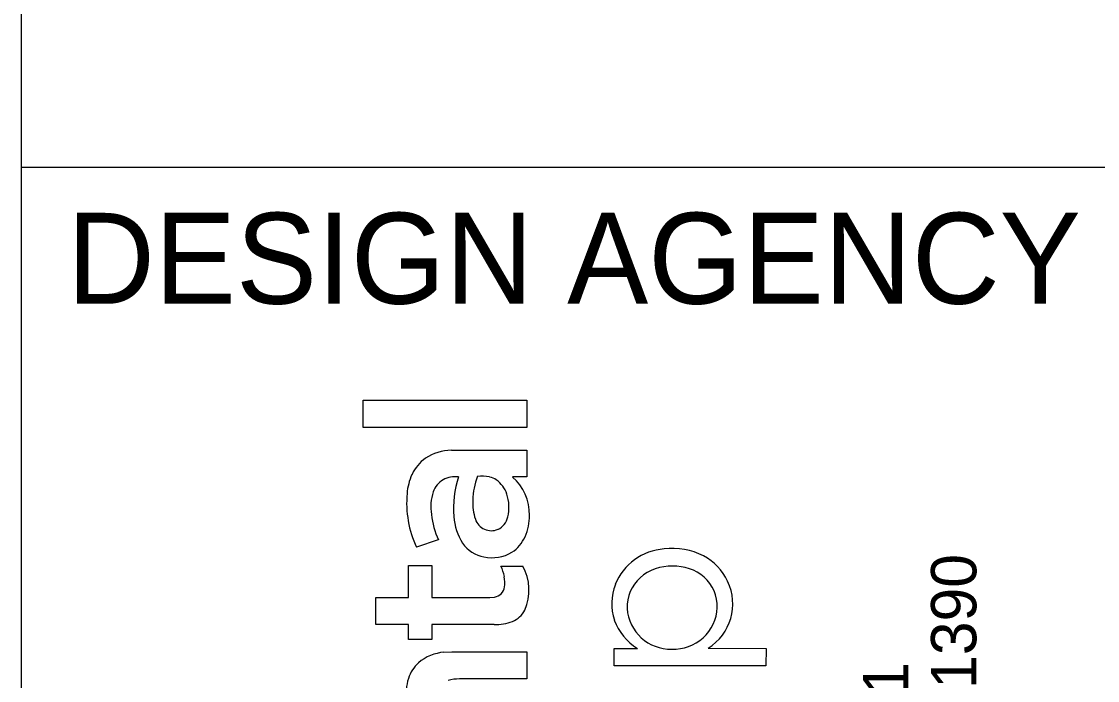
# Model space of a CAD drawing. Extents: x 0 to 34, y 0 to 22.
# Drawn here: x 32 to 33.183, y 3.936 to 4.66 of the extents above; entities that cross this region are included whole.
import ezdxf

# ---------------------------------------------------------------- set-up
doc = ezdxf.new("R2010")
doc.units = 0
doc.layers.add('SH_Border', color=7, linetype='Continuous')
doc.layers.add('SH_Data', color=7, linetype='Continuous')

msp = doc.modelspace()

# ---------------------------------------------------------------- linework, layer by layer
at = {"layer": 'SH_Border'}
for p, q in [((32, 0.5), (32, 21.5)), ((32, 4.5), (33.5, 4.5))]:
    msp.add_line(p, q, dxfattribs=at)
at = {"layer": 'SH_Data'}
for p, q in [((32.3756, 4.2141), (32.3756, 4.244)), ((32.3756, 4.244), (32.5557, 4.244)), ((32.5557, 4.244), (32.5557, 4.2141)), ((32.5557, 4.2141), (32.3756, 4.2141)), ((32.4727, 4.189), (32.5555, 4.1892)), ((32.5555, 4.1892), (32.5557, 4.1596)), ((32.5557, 4.1596), (32.5397, 4.1596)), ((32.4582, 4.0904), (32.4343, 4.0823)), ((32.4254, 4.027), (32.4255, 4.0621)), ((32.4255, 4.0621), (32.4511, 4.0621)), ((32.4511, 4.0621), (32.4512, 4.027)), ((32.527, 4.0616), (32.5511, 4.0616)), ((32.3896, 3.9972), (32.3896, 4.027)), ((32.3896, 4.027), (32.4254, 4.027)), ((32.4512, 4.027), (32.515, 4.027)), ((32.515, 4.027), (32.52, 4.0275)), ((32.4254, 3.9972), (32.3896, 3.9972)), ((32.4254, 3.9807), (32.4254, 3.9972)), ((32.5197, 3.9972), (32.4511, 3.9972)), ((32.4511, 3.9972), (32.4511, 3.9807)), ((32.4511, 3.9807), (32.4254, 3.9807)), ((32.4644, 3.9669), (32.4729, 3.9673)), ((32.4729, 3.9673), (32.5557, 3.9673)), ((32.5557, 3.9673), (32.5557, 3.9375)), ((32.6515, 3.9521), (32.6515, 3.9711)), ((32.6515, 3.9711), (32.6771, 3.9711)), ((32.7549, 3.9713), (32.8186, 3.9711)), ((32.8186, 3.9711), (32.8184, 3.9521)), ((32.8184, 3.9521), (32.6515, 3.9521)), ((32.5557, 3.9375), (32.4814, 3.9375))]:
    msp.add_line(p, q, dxfattribs=at)
msp.add_lwpolyline([(32.3756, 4.2141), (32.3756, 4.244), (32.5557, 4.244), (32.5557, 4.2141)], close=True, dxfattribs=at)
for points in [[(32.4727, 4.189), (32.5555, 4.1892), (32.5557, 4.1596)], [(32.5557, 4.1596), (32.5397, 4.1596)], [(32.4582, 4.0904), (32.4343, 4.0823)], [(32.5197, 3.9972), (32.4511, 3.9972), (32.4511, 3.9807), (32.4254, 3.9807), (32.4254, 3.9972), (32.3896, 3.9972), (32.3896, 4.027), (32.4254, 4.027), (32.4255, 4.0621), (32.4511, 4.0621), (32.4512, 4.027), (32.515, 4.027), (32.52, 4.0275)], [(32.527, 4.0616), (32.5511, 4.0616)], [(32.4644, 3.9669), (32.4729, 3.9673), (32.5557, 3.9673), (32.5557, 3.9375), (32.4814, 3.9375)], [(32.7549, 3.9713), (32.8186, 3.9711), (32.8184, 3.9521), (32.6515, 3.9521)], [(32.6515, 3.9521), (32.6515, 3.9711), (32.6771, 3.9711)]]:
    msp.add_lwpolyline(points, dxfattribs=at)
for centre, radius, start, end in [((32.4745, 4.1326), 0.0565, 91.8942, 122.6317), ((32.4745, 4.1326), 0.0565, 91.8942, 122.6317), ((32.4685, 4.1447), 0.043, 124.537, 155.6594), ((32.4685, 4.1447), 0.043, 124.537, 155.6594), ((32.4882, 4.1361), 0.0646, 155.9764, 175.3149), ((32.4882, 4.1361), 0.0646, 155.9764, 175.3149), ((32.4753, 4.1356), 0.024, 119.4252, 161.6629), ((32.4753, 4.1356), 0.024, 119.4252, 161.6629), ((32.4779, 4.1278), 0.0321, 85.3802, 116.6222), ((32.4779, 4.1278), 0.0321, 85.3802, 116.6222), ((32.5879, 4.1251), 0.1129, 162.0821, 184.5285), ((32.5879, 4.1251), 0.1129, 162.0821, 184.5285), ((32.5801, 4.1313), 0.0841, 159.8366, 178.0362), ((32.5801, 4.1313), 0.0841, 159.8366, 178.0362), ((32.5051, 4.1074), 0.053, 79.6696, 94.2322), ((32.5051, 4.1074), 0.053, 79.6696, 94.2322), ((32.5089, 4.1364), 0.0238, 56.8913, 76.2149), ((32.5089, 4.1364), 0.0238, 56.8913, 76.2149), ((32.5052, 4.1318), 0.0297, 17.5984, 55.7282), ((32.5052, 4.1318), 0.0297, 17.5984, 55.7282), ((32.5055, 4.1191), 0.0529, 358.0746, 49.762), ((32.5055, 4.1191), 0.0529, 358.0746, 49.762), ((32.5364, 4.1308), 0.113, 174.6101, 205.3899), ((32.5364, 4.1308), 0.113, 174.6101, 205.3899), ((32.5076, 4.1265), 0.0576, 163.1369, 188.1675), ((32.5076, 4.1265), 0.0576, 163.1369, 188.1675), ((32.4916, 4.1264), 0.0443, 345.9408, 18.9919), ((32.4916, 4.1264), 0.0443, 345.9408, 18.9919), ((32.5466, 4.1303), 0.0506, 175.5903, 199.8857), ((32.5466, 4.1303), 0.0506, 175.5903, 199.8857), ((32.5473, 4.1297), 0.0973, 186.7598, 203.7981), ((32.5473, 4.1297), 0.0973, 186.7598, 203.7981), ((32.5019, 4.1168), 0.0566, 336.016, 0.5951), ((32.5019, 4.1168), 0.0566, 336.016, 0.5951), ((32.5328, 4.1187), 0.0575, 182.5676, 213.7144), ((32.5328, 4.1187), 0.0575, 182.5676, 213.7144), ((32.5164, 4.1189), 0.0184, 198.2844, 293.3081), ((32.5164, 4.1189), 0.0184, 198.2844, 293.3081), ((32.5152, 4.1199), 0.0199, 295.2883, 347.4639), ((32.5152, 4.1199), 0.0199, 295.2883, 347.4639), ((32.5175, 4.1097), 0.0394, 303.4436, 336.18), ((32.5175, 4.1097), 0.0394, 303.4436, 336.18), ((32.5149, 4.1078), 0.0366, 215.0668, 259.8133), ((32.5149, 4.1078), 0.0366, 215.0668, 259.8133), ((32.7156, 4.0065), 0.0746, 62.6889, 97.0135), ((32.7156, 4.0065), 0.0746, 62.6889, 97.0135), ((32.5175, 4.1131), 0.0423, 257.5256, 300.882), ((32.5175, 4.1131), 0.0423, 257.5256, 300.882), ((32.7108, 4.0182), 0.0624, 93.9866, 158.3119), ((32.7108, 4.0182), 0.0624, 93.9866, 158.3119), ((32.7212, 4.0191), 0.0608, 25.0657, 61.9602), ((32.7212, 4.0191), 0.0608, 25.0657, 61.9602), ((32.4863, 4.042), 0.0452, 10.1545, 25.723), ((32.4863, 4.042), 0.0452, 10.1545, 25.723), ((32.503, 4.0351), 0.0549, 336.589, 28.8991), ((32.503, 4.0351), 0.0549, 336.589, 28.8991), ((32.7138, 4.0102), 0.0513, 87.8965, 131.1812), ((32.7138, 4.0102), 0.0513, 87.8965, 131.1812), ((32.7175, 4.0102), 0.0513, 49.9089, 92.0363), ((32.7175, 4.0102), 0.0513, 49.9089, 92.0363), ((32.4957, 4.0436), 0.0356, 351.914, 10.2059), ((32.4957, 4.0436), 0.0356, 351.914, 10.2059), ((32.7092, 4.0167), 0.0434, 132.3289, 182.0949), ((32.7092, 4.0167), 0.0434, 132.3289, 182.0949), ((32.7215, 4.0173), 0.0433, 358.0487, 47.9447), ((32.7215, 4.0173), 0.0433, 358.0487, 47.9447), ((32.5184, 4.04), 0.0126, 277.6142, 353.7918), ((32.5184, 4.04), 0.0126, 277.6142, 353.7918), ((32.707, 4.0202), 0.0581, 158.656, 198.171), ((32.707, 4.0202), 0.0581, 158.656, 198.171), ((32.7245, 4.02), 0.0574, 301.9776, 25.6418), ((32.7245, 4.02), 0.0574, 301.9776, 25.6418), ((32.5291, 4.0261), 0.0275, 292.6889, 332.0598), ((32.5291, 4.0261), 0.0275, 292.6889, 332.0598), ((32.7135, 4.0181), 0.0478, 183.5974, 271.7045), ((32.7135, 4.0181), 0.0478, 183.5974, 271.7045), ((32.7172, 4.018), 0.0477, 267.3149, 357.4019), ((32.7172, 4.018), 0.0477, 267.3149, 357.4019), ((32.5209, 4.0486), 0.0514, 268.6727, 291.5235), ((32.5209, 4.0486), 0.0514, 268.6727, 291.5235), ((32.7103, 4.0243), 0.0627, 200.8399, 238.0162), ((32.7103, 4.0243), 0.0627, 200.8399, 238.0162), ((32.4687, 3.9172), 0.0499, 94.9706, 130.2248), ((32.4687, 3.9172), 0.0499, 94.9706, 130.2248), ((32.4635, 3.9255), 0.0402, 132.2238, 161.6823), ((32.4635, 3.9255), 0.0402, 132.2238, 161.6823), ((32.4787, 3.9211), 0.056, 162.274, 187.7917), ((32.4787, 3.9211), 0.056, 162.274, 187.7917), ((32.4811, 3.8915), 0.046, 89.6051, 105.3303), ((32.4811, 3.8915), 0.046, 89.6051, 105.3303)]:
    msp.add_arc(centre, radius, start, end, dxfattribs=at)

# ---------------------------------------------------------------- texts
msp.add_text('DESIGN AGENCY', height=0.1, dxfattribs=at).set_placement((32.05, 4.35))
for s, p in [('800.835.1390', (33.0497, 3.6671)), ('450 GRANT ST., AKRON, OH  44311', (32.9749, 2.8374))]:
    msp.add_text(s, height=0.049846, rotation=90, dxfattribs=at).set_placement(p)

doc.saveas('drawing.dxf')
